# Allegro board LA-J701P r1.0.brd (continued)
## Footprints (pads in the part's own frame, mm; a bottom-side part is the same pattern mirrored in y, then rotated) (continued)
ACES_51524-00401-001_4P
  oval 0.61x1.448 smd: 1(0,0) 2(1,0) 3(2,0) 4(3,0)
  rect 2.388x2.21 smd: 5(-3,-3.125) 6(6,-3.125)
ACES_51612-0340M-P01_34P-T
  oval 0.508x1.245 smd: 1(0,0) 2(0.8,0) 3(1.6,0) 4(2.4,0) 5(3.2,0) 6(4,0) 7(4.8,0) 8(5.6,0) 9(6.4,0) 10(7.2,0) 11(8,0) 12(8.8,0) 13(9.6,0) 14(10.4,0) 15(11.2,0) 16(12,0) 17(12.8,0) 18(13.6,0) 19(14.4,0) 20(15.2,0) 21(16,0) 22(16.8,0) 23(17.6,0) 24(18.4,0) 25(19.2,0) 26(20,0) 27(20.8,0) 28(21.6,0) 29(22.4,0) 30(23.2,0) 31(24,0) 32(24.8,0) 33(25.6,0) 34(26.4,0)
  rect 1.397x1.194 smd: 35(29.075,-3.275) 36(-2.675,-3.275)
ACES_60757-00802-001_8P-T
  oval 0.787x1.295 smd: 1(0,0) 2(-1.25,0) 3(-2.5,0) 4(-3.75,0) 5(-5,0) 6(-6.25,0) 7(-7.5,0) 8(-8.75,0)
  oval 1.041x1.651 hole 0.66x1.245: 9(1.75,-2.8) 10(1.75,-6.275) 11(-10.5,-6.275) 12(-10.5,-2.8)
ALC3287-CG_MQFN48_6X6
  oval 0.889x0.203 smd: 1(0,0) 2(0,-0.4) 3(0,-0.8) 4(0,-1.2) 5(0,-1.6) 6(0,-2) 7(0,-2.4) 8(0,-2.8) 9(0,-3.2) 10(0,-3.6) 11(0,-4) 12(0,-4.4) 25(6.1,-4.4) 26(6.1,-4) 27(6.1,-3.6) 28(6.1,-3.2) 29(6.1,-2.8) 30(6.1,-2.4) 31(6.1,-2) 32(6.1,-1.6) 33(6.1,-1.2) 34(6.1,-0.8) 35(6.1,-0.4) 36(6.1,0)
  oval 0.203x0.889 smd: 13(0.85,-5.25) 14(1.25,-5.25) 15(1.65,-5.25) 16(2.05,-5.25) 17(2.45,-5.25) 18(2.85,-5.25) 19(3.25,-5.25) 20(3.65,-5.25) 21(4.05,-5.25) 22(4.45,-5.25) 23(4.85,-5.25) 24(5.25,-5.25) 37(5.25,0.85) 38(4.85,0.85) 39(4.45,0.85) 40(4.05,0.85) 41(3.65,0.85) 42(3.25,0.85) 43(2.85,0.85) 44(2.45,0.85) 45(2.05,0.85) 46(1.65,0.85) 47(1.25,0.85) 48(0.85,0.85)
  rect 4.394x4.394 smd: 49(3.05,-2.2)
AON6962_DFN5X6D-8-7
  oval 0.66x0.635 smd: 1(0,0) 3(3.81,5.67) 4(2.54,5.67) 5(1.27,5.67) 6(0,5.67)
  custom 0.485x0.485 smd: 2(1.905,0.655)
  rect 3.988x2.667 smd: 7(1.905,3.63)
AON6992_DFN5X6D-8-7
  oval 0.66x0.635 smd: 1(0,0) 3(3.81,5.67) 4(2.54,5.67) 5(1.27,5.67) 6(0,5.67)
  custom 0.485x0.485 smd: 2(1.905,0.655)
  rect 3.988x2.667 smd: 7(1.905,3.62)
AON6994_DFN5X6D-8-7
  oval 0.66x0.635 smd: 1(0,0) 3(3.81,5.67) 4(2.54,5.67) 5(1.27,5.67) 6(0,5.67)
  custom 0.485x0.485 smd: 2(1.905,0.665)
  rect 3.988x2.667 smd: 7(1.905,3.63)
AON7408L_DFN8-5
  oval 0.406x0.991 smd: 1(0,0) 2(0.66,0) 3(1.32,0) 4(1.98,0)
  custom 0.559x0.559 smd: 5(0.99,2.247)
AON7506_DFN3X3-8-5
  oval 0.406x0.991 smd: 1(0,0) 2(0.66,0) 3(1.32,0) 4(1.98,0)
  custom 0.559x0.559 smd: 5(0.99,2.247)
AP2330W-7_SC59-3
  oval 0.787x0.991 smd: 1(0,0) 2(-0.95,-2.4) 3(0.95,-2.4)
AZ5125-02SPR7G_SOT23-3
  oval 1.016x1.524 smd: 1(0,0) 2(0.965,2.083) 3(-0.965,2.083)
AZC099-04SPR7G_SOT23-6
  oval 0.559x1.092 smd: 1(0,0) 2(0.95,0) 3(1.9,0) 4(1.9,2.5) 5(0.95,2.5) 6(0,2.5)
BAT54CW_SOT323-3
  oval 0.711x0.889 smd: 1(0,0) 2(-0.65,-1.9) 3(0.65,-1.9)
BELLW_80152-3221_67P
  round 1.092 hole 1.092 unplated: (-0.75,-5.275)
  round 1.6 hole 1.6 unplated: (19.25,-5.275)
  oval 0.305x1.549 smd: 1(0,0) 2(0.25,-7.55) 3(0.5,0) 4(0.75,-7.55) 5(1,0) 6(1.25,-7.55) 7(1.5,0) 8(1.75,-7.55) 9(2,0) 10(2.25,-7.55) 11(2.5,0) 12(2.75,-7.55) 13(3,0) 14(3.25,-7.55) 15(3.5,0) 16(3.75,-7.55) 17(4,0) 18(4.25,-7.55) 19(4.5,0) 20(4.75,-7.55) 21(5,0) 22(5.25,-7.55) 23(5.5,0) 24(7.75,-7.55) 25(8,0) 26(8.25,-7.55) 27(8.5,0) 28(8.75,-7.55) 29(9,0) 30(9.25,-7.55) 31(9.5,0) 32(9.75,-7.55) 33(10,0) 34(10.25,-7.55) 35(10.5,0) 36(10.75,-7.55) 37(11,0) 38(11.25,-7.55) 39(11.5,0) 40(11.75,-7.55) 41(12,0) 42(12.25,-7.55) 43(12.5,0) 44(12.75,-7.55) 45(13,0) 46(13.25,-7.55) 47(13.5,0) 48(13.75,-7.55) 49(14,0) 50(14.25,-7.55) 51(14.5,0) 52(14.75,-7.55) 53(15,0) 54(15.25,-7.55) 55(15.5,0) 56(15.75,-7.55) 57(16,0) 58(16.25,-7.55) 59(16.5,0) 60(16.75,-7.55) 61(17,0) 62(17.25,-7.55) 63(17.5,0) 64(17.75,-7.55) 65(18,0) 66(18.25,-7.55) 67(18.5,0)
  rect 1.194x2.743 smd: 68(-1.1,-0.775) 69(19.6,-0.775)
BELLW_80159-3221_67P
  round 1.092 hole 1.092 unplated: (-0.75,-5.275)
  round 1.6 hole 1.6 unplated: (19.25,-5.275)
  oval 0.305x1.549 smd: 1(0,0) 2(0.25,-7.55) 3(0.5,0) 4(0.75,-7.55) 5(1,0) 6(1.25,-7.55) 7(1.5,0) 8(1.75,-7.55) 9(2,0) 10(2.25,-7.55) 11(2.5,0) 12(2.75,-7.55) 13(3,0) 14(3.25,-7.55) 15(3.5,0) 16(3.75,-7.55) 17(4,0) 18(4.25,-7.55) 19(4.5,0) 20(4.75,-7.55) 21(5,0) 22(5.25,-7.55) 23(5.5,0) 24(5.75,-7.55) 25(6,0) 26(6.25,-7.55) 27(6.5,0) 28(6.75,-7.55) 29(7,0) 30(7.25,-7.55) 31(7.5,0) 32(7.75,-7.55) 33(8,0) 34(8.25,-7.55) 35(8.5,0) 36(8.75,-7.55) 37(9,0) 38(9.25,-7.55) 39(9.5,0) 40(9.75,-7.55) 41(10,0) 42(10.25,-7.55) 43(10.5,0) 44(10.75,-7.55) 45(11,0) 46(11.25,-7.55) 47(11.5,0) 48(11.75,-7.55) 49(12,0) 50(12.25,-7.55) 51(12.5,0) 52(12.75,-7.55) 53(13,0) 54(13.25,-7.55) 55(13.5,0) 56(13.75,-7.55) 57(14,0) 58(14.25,-7.55) 59(16.5,0) 60(16.75,-7.55) 61(17,0) 62(17.25,-7.55) 63(17.5,0) 64(17.75,-7.55) 65(18,0) 66(18.25,-7.55) 67(18.5,0)
  rect 1.194x2.743 smd: 68(-1.1,-0.775) 69(19.6,-0.775)
BQ25700ARSNR_QFN32_4X4
  oval 0.838x0.203 smd: 1(0,0) 2(0,-0.4) 3(0,-0.8) 4(0,-1.2) 5(0,-1.6) 6(0,-2) 7(0,-2.4) 8(0,-2.8) 17(4.15,-2.8) 18(4.15,-2.4) 19(4.15,-2) 20(4.15,-1.6) 21(4.15,-1.2) 22(4.15,-0.8) 23(4.15,-0.4) 24(4.15,0)
  oval 0.203x0.838 smd: 9(0.675,-3.475) 10(1.075,-3.475) 11(1.475,-3.475) 12(1.875,-3.475) 13(2.275,-3.475) 14(2.675,-3.475) 15(3.075,-3.475) 16(3.475,-3.475) 25(3.475,0.675) 26(3.075,0.675) 27(2.675,0.675) 28(2.275,0.675) 29(1.875,0.675) 30(1.475,0.675) 31(1.075,0.675) 32(0.675,0.675)
  rect 2.794x2.794 smd: 33(2.075,-1.4)
BZT52-B5V1S_SOD323-2
  rect 0.559x0.813 smd: 1(0,0) 2(2.3,0)
C_6P3X4P5
  oval 3.505x1.6 smd: 1(0,0) 2(5.6,0)
C_0201
  rect 0.381x0.356 smd: 1(0,0) 2(0.584,0)
C_0402
  rect 0.508x0.584 smd: 1(0,0) 2(0.914,0)
C_0603
  rect 0.635x0.889 smd: 1(0,0) 2(1.397,0)
C_0805
  rect 0.813x1.397 smd: 1(0,0) 2(1.702,0)
C_D2
  rect 2.388x2.794 smd: 1(0,0) 2(6.4,0)
C_D7
  rect 1.803x2.794 smd: 1(0,0) 2(6.5,0)
C_X
  rect 1.803x2.896 smd: 1(0,0) 2(6,0)
CVILU_CVS3402M1RM-NH_40P
  oval 0.254x1.295 smd: 1(0,0) 2(0.5,0) 3(1,0) 4(1.5,0) 5(2,0) 6(2.5,0) 7(3,0) 8(3.5,0) 9(4,0) 10(4.5,0) 11(5,0) 12(5.5,0) 13(6,0) 14(6.5,0) 15(7,0) 16(7.5,0) 17(8,0) 18(8.5,0) 19(9,0) 20(9.5,0) 21(10,0) 22(10.5,0) 23(11,0) 24(11.5,0) 25(12,0) 26(12.5,0) 27(13,0) 28(13.5,0) 29(14,0) 30(14.5,0) 31(15,0) 32(15.5,0) 33(16,0) 34(16.5,0) 35(17,0) 36(17.5,0) 37(18,0) 38(18.5,0) 39(19,0) 40(19.5,0)
  rect 1.194x3.2 smd: 41(-2.4,1.95) 45(21.9,1.95)
  rect 2.311x1.295 smd: 42(0.85,3.9) 43(9.75,3.9) 44(18.65,3.9)
CYNTE_PCMB103T-2R2MS_2P
  rect 3.81x3.988 smd: 1(0,0) 2(9.2,0)
D_SOD323-2
  rect 0.787x0.889 smd: 1(0,0) 2(2.14,0)
DPS1113FIA-13_QFN18_4X4
  oval 0.762x1.295 smd: 1(0,0) 13(3.85,0)
  oval 0.762x0.305 smd: 2(0,-1) 3(0,-1.5) 4(0,-2) 10(3.85,-2) 11(3.85,-1.5) 12(3.85,-1)
  oval 0.305x0.762 smd: 5(0.925,-2.925) 6(1.425,-2.925) 7(1.925,-2.925) 8(2.425,-2.925) 9(2.925,-2.925)
  rect 2.591x2.972 smd: 14(1.925,-0.813)
DPS1155FEA_V-QFN3025-20_3X2P5
  oval 0.61x0.203 smd: 1(0,0) 2(0,-0.4) 3(0,-0.8) 4(0,-1.2) 5(0,-1.6) 6(0,-2) 9(2.8,-2) 10(2.8,-1.6) 11(2.8,-1.2) 12(2.8,-0.8) 13(2.8,-0.4) 14(2.8,0)
  custom 0.194x0.194 smd: 7(0.913,-1) 8(1.887,-1)
DRAPH_UB11245-B200B-1H_24P-S
  round 0.711 hole 0.711 unplated: (-0.8,-0.776)
  round 0.66 hole 0.66 unplated: (6.55,-0.776)
  oval 0.889x2.311 hole 0.508x1.905: 1(-3.025,-6.876) 3(-2.075,-0.876) 4(7.825,-0.876) 6(8.775,-6.876)
  custom 0.191x0.191 hole 0.711x0.457: 2(-0.9,-1.706)
  oval 1.016x0.762 hole 0.711x0.457: 5(6.65,-1.706)
  oval 0.305x0.787 smd: A1(0,0) A2(0.5,0) A3(1,0) A4(1.5,0) A5(2,0) A6(2.5,0) A7(3,0) A8(3.5,0) A9(4,0) A10(4.5,0) A11(5,0) A12(5.5,0) B1(5.75,-1.452) B2(5.25,-1.452) B3(4.75,-1.452) B4(4.25,-1.452) B5(3.75,-1.452) B6(3.25,-1.452) B7(2.75,-1.452) B8(2.25,-1.452) B9(1.75,-1.452) B10(1.25,-1.452) B11(0.75,-1.452) B12(0.25,-1.452)
EM5201V_DFN8_3X3
  oval 0.305x0.61 smd: 1(0,0) 2(0.65,0) 3(1.3,0) 4(1.95,0) 5(1.95,2.8)
  rect 1.6x0.61 smd: 6(0.65,2.8)
  rect 2.388x1.6 smd: 7(0.975,1.4)
EM5209VF_DFN14_3X2
  oval 0.203x0.711 smd: 1(0,0) 2(0.4,0) 3(0.8,0) 4(1.2,0) 5(1.6,0) 6(2,0) 7(2.4,0) 8(2.4,2) 9(2,2) 10(1.6,2) 11(1.2,2) 12(0.8,2) 13(0.4,2) 14(0,2)
  rect 2.591x0.991 smd: 15(1.2,1)
F75305M_MSOP10
  oval 0.254x1.626 smd: 1(0,0) 2(0.5,0) 3(1,0) 4(1.5,0) 5(2,0) 6(2,4.3) 7(1.5,4.3) 8(1,4.3) 9(0.5,4.3) 10(0,4.3)
  rect 1.6x1.727 smd: 11(1,2.15)
F_F1206HB12V024TM
  rect 1.448x1.803 smd: 1(0,0) 2(2.95,0)
F_F1206HI7000V024TM
  rect 1.448x1.803 smd: 1(0,0) 2(2.95,0)
FIDUCIAL_C40M80
  round 1.016 smd: 1(0,0)
FP6_BGA_1140P-T
  round 0.305 smd: A3(0.9,0) A5(1.8,0) A7(3.3,0) A8(4.3,0) A10(5.3,0) A11(6.3,0) A12(7.3,0) A13(8.3,0) A14(9.3,0) A15(10.3,0) A16(11.3,0) A18(12.3,0) A19(13.3,0) A20(14.3,0) A21(15.3,0) A22(16.3,0) A23(17.3,0) A25(18.3,0) A26(19.3,0) A28(20.8,0) A30(21.7,0) AA1(0,-15.3) AA2(0.4,-14.8) AA3(0.8,-15.3) AA4(1.2,-14.8) AA5(1.9,-15.3) AA13(8.5,-15.1) AA14(9.3,-15.1) AA15(10.1,-15.1) AA16(10.9,-15.1) AA17(11.7,-15.1) AA18(12.5,-15.1) AA19(13.3,-15.1) AA20(14.1,-15.1) AA28(20.7,-15.3) AA29(21.4,-14.8) AA30(21.8,-15.3) AA31(22.2,-14.8) AA32(22.6,-15.3) AB2(0.4,-15.8) AB4(1.2,-15.8) AB13(8.5,-15.9) AB14(9.3,-15.9) AB15(10.1,-15.9) AB16(10.9,-15.9) AB17(11.7,-15.9) AB18(12.5,-15.9) AB19(13.3,-15.9) AB20(14.1,-15.9) AB29(21.4,-15.8) AB31(22.2,-15.8) AC1(0,-16.3) AC2(0.4,-16.8) AC3(0.8,-16.3) AC4(1.2,-16.8) AC5(1.9,-16.3) AC13(8.5,-16.7) AC14(9.3,-16.7) AC15(10.1,-16.7) AC16(10.9,-16.7) AC17(11.7,-16.7) AC18(12.5,-16.7) AC19(13.3,-16.7) AC20(14.1,-16.7) AC28(20.7,-16.3) AC29(21.4,-16.8) AC30(21.8,-16.3) AC31(22.2,-16.8) AC32(22.6,-16.3) AD1(0,-17.3) AD2(0.4,-17.8) AD3(0.8,-17.3) AD4(1.2,-17.8) AD5(1.9,-17.3) AD13(8.5,-17.5) AD14(9.3,-17.5) AD15(10.1,-17.5) AD16(10.9,-17.5) AD17(11.7,-17.5) AD18(12.5,-17.5) AD19(13.3,-17.5) AD20(14.1,-17.5) AD28(20.7,-17.3) AD29(21.4,-17.8) AD30(21.8,-17.3) AD31(22.2,-17.8) AD32(22.6,-17.3) AE1(0,-18.3) AE3(0.8,-18.3) AE5(1.9,-18.3) AE13(8.5,-18.3) AE14(9.3,-18.3) AE15(10.1,-18.3) AE16(10.9,-18.3) AE17(11.7,-18.3) AE18(12.5,-18.3) AE19(13.3,-18.3) AE20(14.1,-18.3) AE28(20.7,-18.3) AE30(21.8,-18.3) AE32(22.6,-18.3) AF1(0,-19.3) AF2(0.4,-18.8) AF3(0.8,-19.3) AF4(1.2,-18.8) AF5(1.9,-19.3) AF13(8.5,-19.1) AF14(9.3,-19.1) AF15(10.1,-19.1) AF16(10.9,-19.1) AF17(11.7,-19.1) AF18(12.5,-19.1) AF19(13.3,-19.1) AF20(14.1,-19.1) AF28(20.7,-19.3) AF29(21.4,-18.8) AF30(21.8,-19.3) AF31(22.2,-18.8) AF32(22.6,-19.3) AG1(0,-20.3) AG2(0.4,-19.8) AG3(0.8,-20.3) AG4(1.2,-19.8) AG5(1.9,-20.3) AG13(8.5,-19.9) AG14(9.3,-19.9) AG15(10.1,-19.9) AG16(10.9,-19.9) AG17(11.7,-19.9) AG18(12.5,-19.9) AG19(13.3,-19.9) AG20(14.1,-19.9) AG28(20.7,-20.3) AG29(21.4,-19.8) AG30(21.8,-20.3) AG31(22.2,-19.8) AG32(22.6,-20.3) AH2(0.4,-20.8) AH4(1.2,-20.8) AH13(8.5,-20.7) AH14(9.3,-20.7) AH15(10.1,-20.7) AH16(10.9,-20.7) AH17(11.7,-20.7) AH18(12.5,-20.7) AH19(13.3,-20.7) AH20(14.1,-20.7) AH29(21.4,-20.8) AH31(22.2,-20.8) AJ1(0,-21.3) AJ2(0.4,-21.8) AJ3(0.8,-21.3) AJ4(1.2,-21.8) AJ5(1.9,-21.3) AJ13(8.5,-21.5) AJ14(9.3,-21.5) AJ15(10.1,-21.5) AJ16(10.9,-21.5) AJ17(11.7,-21.5) AJ18(12.5,-21.5) AJ19(13.3,-21.5) AJ20(14.1,-21.5) AJ28(20.7,-21.3) AJ29(21.4,-21.8) AJ30(21.8,-21.3) AJ31(22.2,-21.8) AJ32(22.6,-21.3) AK1(0,-22.3) AK3(0.8,-22.3) AK5(1.9,-22.3) AK13(8.5,-22.3) AK14(9.3,-22.3) AK15(10.1,-22.3) AK16(10.9,-22.3) AK17(11.7,-22.3) AK18(12.5,-22.3) AK19(13.3,-22.3) AK20(14.1,-22.3) AK28(20.7,-22.3) AK30(21.8,-22.3) AK32(22.6,-22.3) AL1(0,-23.3) AL2(0.4,-22.8) AL3(0.8,-23.3) AL4(1.2,-22.8) AL5(1.9,-23.3) AL13(8.5,-23.1) AL14(9.3,-23.1) AL15(10.1,-23.1) AL16(10.9,-23.1) AL17(11.7,-23.1) AL18(12.5,-23.1) AL19(13.3,-23.1) AL20(14.1,-23.1) AL28(20.7,-23.3) AL29(21.4,-22.8) AL30(21.8,-23.3) AL31(22.2,-22.8) AL32(22.6,-23.3) AM1(0,-24.3) AM2(0.4,-23.8) AM3(0.8,-24.3) AM4(1.2,-23.8) AM5(1.9,-24.3) AM13(8.5,-23.9) AM14(9.3,-23.9) AM15(10.1,-23.9) AM16(10.9,-23.9) AM17(11.7,-23.9) AM18(12.5,-23.9) AM19(13.3,-23.9) AM20(14.1,-23.9) AM28(20.7,-24.3) AM29(21.4,-23.8) AM30(21.8,-24.3) AM31(22.2,-23.8) AM32(22.6,-24.3) AN1(0,-25.3) AN2(0.4,-24.8) AN3(0.8,-25.3) AN4(1.2,-24.8) AN5(1.9,-25.3) AN28(20.7,-25.3) AN29(21.4,-24.8) AN30(21.8,-25.3) AN31(22.2,-24.8) AN32(22.6,-25.3) AP1(0,-26.3) AP2(0.4,-25.8) AP3(0.8,-26.3) AP4(1.2,-25.8) AP5(1.9,-26.3) AP28(20.7,-26.3) AP29(21.4,-25.8) AP30(21.8,-26.3) AP31(22.2,-25.8) AP32(22.6,-26.3) AR1(0,-27.3) AR2(0.4,-26.8) AR3(0.8,-27.3) AR4(1.2,-26.8) AR5(1.9,-27.3) AR28(20.7,-27.3) AR29(21.4,-26.8) AR30(21.8,-27.3) AR31(22.2,-26.8) AR32(22.6,-27.3) AT2(0.4,-27.8) AT4(1.2,-27.8) AT29(21.4,-27.8) AT31(22.2,-27.8) AU1(0,-28.3) AU2(0.4,-28.8) AU3(0.8,-28.3) AU4(1.2,-28.8) AU5(1.9,-28.3) AU28(20.7,-28.3) AU29(21.4,-28.8) AU30(21.8,-28.3) AU31(22.2,-28.8) AU32(22.6,-28.3) AV1(0,-29.3) AV3(0.8,-29.3) AV5(1.9,-29.3) AV28(20.7,-29.3) AV30(21.8,-29.3) AV32(22.6,-29.3) AW2(0.4,-29.8) AW3(0.8,-30.3) AW4(1.2,-29.8) AW5(1.8,-30.3) AW28(20.8,-30.3) AW29(21.4,-29.8) AW30(21.8,-30.3) AW31(22.2,-29.8) AY1(0,-30.8) AY4(1.2,-30.8) AY6(2.3,-30.8) AY7(3.3,-30.7) AY8(4.3,-30.7) AY10(5.3,-30.7) AY11(6.3,-30.7) AY12(7.3,-30.7) AY13(8.3,-30.7) AY14(9.3,-30.7) AY15(10.3,-30.7) AY16(11.3,-30.7) AY18(12.3,-30.7) AY19(13.3,-30.7) AY20(14.3,-30.7) AY21(15.3,-30.7) AY22(16.3,-30.7) AY23(17.3,-30.7) AY25(18.3,-30.7) AY26(19.3,-30.7) AY27(20.3,-30.8) AY29(21.4,-30.8) AY32(22.6,-30.8) B6(2.8,-0.4) B8(3.8,-0.4) B9(4.8,-0.4) B10(5.8,-0.4) B11(6.8,-0.4) B12(7.8,-0.4) B13(8.8,-0.4) B15(9.8,-0.4) B16(10.8,-0.4) B17(11.8,-0.4) B18(12.8,-0.4) B20(13.8,-0.4) B21(14.8,-0.4) B22(15.8,-0.4) B23(16.8,-0.4) B24(17.8,-0.4) B25(18.8,-0.4) B27(19.8,-0.4) BA5(1.8,-31.4) BA6(2.8,-31.4) BA8(3.8,-31.4) BA9(4.8,-31.4) BA10(5.8,-31.4) BA11(6.8,-31.4) BA12(7.8,-31.4) BA13(8.8,-31.4) BA15(9.8,-31.4) BA16(10.8,-31.4) BA17(11.8,-31.4) BA18(12.8,-31.4) BA20(13.8,-31.4) BA21(14.8,-31.4) BA22(15.8,-31.4) BA23(16.8,-31.4) BA24(17.8,-31.4) BA25(18.8,-31.4) BA27(19.8,-31.4) BA28(20.8,-31.4) BB1(0,-31.7) BB3(0.9,-31.7) BB6(2.3,-31.8) BB7(3.3,-31.8) BB8(4.3,-31.8) BB10(5.3,-31.8) BB11(6.3,-31.8) BB12(7.3,-31.8) BB13(8.3,-31.8) BB14(9.3,-31.8) BB15(10.3,-31.8) BB16(11.3,-31.8) BB18(12.3,-31.8) BB19(13.3,-31.8) BB20(14.3,-31.8) BB21(15.3,-31.8) BB22(16.3,-31.8) BB23(17.3,-31.8) BB25(18.3,-31.8) BB26(19.3,-31.8) BB27(20.3,-31.8) BB30(21.7,-31.7) BB32(22.6,-31.7) BC6(2.8,-32.2) BC8(3.8,-32.2) BC9(4.8,-32.2) BC10(5.8,-32.2) BC11(6.8,-32.2) BC12(7.8,-32.2) BC13(8.8,-32.2) BC15(9.8,-32.2) BC16(10.8,-32.2) BC17(11.8,-32.2) BC18(12.8,-32.2) BC20(13.8,-32.2) BC21(14.8,-32.2) BC22(15.8,-32.2) BC23(16.8,-32.2) BC24(17.8,-32.2) BC25(18.8,-32.2) BC27(19.8,-32.2) BD3(0.9,-32.6) BD5(1.8,-32.6) BD7(3.3,-32.6) BD8(4.3,-32.6) BD10(5.3,-32.6) BD11(6.3,-32.6) BD12(7.3,-32.6) BD13(8.3,-32.6) BD14(9.3,-32.6) BD15(10.3,-32.6) BD16(11.3,-32.6) BD18(12.3,-32.6) BD19(13.3,-32.6) BD20(14.3,-32.6) BD21(15.3,-32.6) BD22(16.3,-32.6) BD23(17.3,-32.6) BD25(18.3,-32.6) BD26(19.3,-32.6) BD28(20.8,-32.6) BD30(21.7,-32.6) C1(0,-0.9) C3(0.9,-0.9) C6(2.3,-0.8) C7(3.3,-0.8) C8(4.3,-0.8) C10(5.3,-0.8) C11(6.3,-0.8) C12(7.3,-0.8) C13(8.3,-0.8) C14(9.3,-0.8) C15(10.3,-0.8) C16(11.3,-0.8) C18(12.3,-0.8) C19(13.3,-0.8) C20(14.3,-0.8) C21(15.3,-0.8) C22(16.3,-0.8) C23(17.3,-0.8) C25(18.3,-0.8) C26(19.3,-0.8) C27(20.3,-0.8) C30(21.7,-0.9) C32(22.6,-0.9) D5(1.8,-1.2) D6(2.8,-1.2) D8(3.8,-1.2) D9(4.8,-1.2) D10(5.8,-1.2) D11(6.8,-1.2) D12(7.8,-1.2) D13(8.8,-1.2) D15(9.8,-1.2) D16(10.8,-1.2) D17(11.8,-1.2) D18(12.8,-1.2) D20(13.8,-1.2) D21(14.8,-1.2) D22(15.8,-1.2) D23(16.8,-1.2) D24(17.8,-1.2) D25(18.8,-1.2) D27(19.8,-1.2) D28(20.8,-1.2) E1(0,-1.8) E4(1.2,-1.8) E6(2.3,-1.8) E7(3.3,-1.9) E8(4.3,-1.9) E10(5.3,-1.9) E11(6.3,-1.9) E12(7.3,-1.9) E13(8.3,-1.9) E14(9.3,-1.9) E15(10.3,-1.9) E16(11.3,-1.9) E18(12.3,-1.9) E19(13.3,-1.9) E20(14.3,-1.9) E21(15.3,-1.9) E22(16.3,-1.9) E23(17.3,-1.9) E25(18.3,-1.9) E26(19.3,-1.9) E27(20.3,-1.8) E29(21.4,-1.8) E32(22.6,-1.8) F2(0.4,-2.8) F3(0.8,-2.3) F4(1.2,-2.8) F5(1.8,-2.3) F28(20.8,-2.3) F29(21.4,-2.8) F30(21.8,-2.3) F31(22.2,-2.8) G1(0,-3.3) G3(0.8,-3.3) G5(1.9,-3.3) G28(20.7,-3.3) G30(21.8,-3.3) G32(22.6,-3.3) H1(0,-4.3) H2(0.4,-3.8) H3(0.8,-4.3) H4(1.2,-3.8) H5(1.9,-4.3) H28(20.7,-4.3) H29(21.4,-3.8) H30(21.8,-4.3) H31(22.2,-3.8) H32(22.6,-4.3) J2(0.4,-4.8) J4(1.2,-4.8) J29(21.4,-4.8) J31(22.2,-4.8) K1(0,-5.3) K2(0.4,-5.8) K3(0.8,-5.3) K4(1.2,-5.8) K5(1.9,-5.3) K28(20.7,-5.3) K29(21.4,-5.8) K30(21.8,-5.3) K31(22.2,-5.8) K32(22.6,-5.3) L1(0,-6.3) L2(0.4,-6.8) L3(0.8,-6.3) L4(1.2,-6.8) L5(1.9,-6.3) L28(20.7,-6.3) L29(21.4,-6.8) L30(21.8,-6.3) L31(22.2,-6.8) L32(22.6,-6.3) M1(0,-7.3) M2(0.4,-7.8) M3(0.8,-7.3) M4(1.2,-7.8) M5(1.9,-7.3) M28(20.7,-7.3) M29(21.4,-7.8) M30(21.8,-7.3) M31(22.2,-7.8) M32(22.6,-7.3) N1(0,-8.3) N2(0.4,-8.8) N3(0.8,-8.3) N4(1.2,-8.8) N5(1.9,-8.3) N13(8.5,-8.7) N14(9.3,-8.7) N15(10.1,-8.7) N16(10.9,-8.7) N17(11.7,-8.7) N18(12.5,-8.7) N19(13.3,-8.7) N20(14.1,-8.7) N28(20.7,-8.3) N29(21.4,-8.8) N30(21.8,-8.3) N31(22.2,-8.8) N32(22.6,-8.3) P1(0,-9.3) P2(0.4,-9.8) P3(0.8,-9.3) P4(1.2,-9.8) P5(1.9,-9.3) P13(8.5,-9.5) P14(9.3,-9.5) P15(10.1,-9.5) P16(10.9,-9.5) P17(11.7,-9.5) P18(12.5,-9.5) P19(13.3,-9.5) P20(14.1,-9.5) P28(20.7,-9.3) P29(21.4,-9.8) P30(21.8,-9.3) P31(22.2,-9.8) P32(22.6,-9.3) R1(0,-10.3) R3(0.8,-10.3) R5(1.9,-10.3) R13(8.5,-10.3) R14(9.3,-10.3) R15(10.1,-10.3) R16(10.9,-10.3) R17(11.7,-10.3) R18(12.5,-10.3) R19(13.3,-10.3) R20(14.1,-10.3) R28(20.7,-10.3) R30(21.8,-10.3) R32(22.6,-10.3) T1(0,-11.3) T2(0.4,-10.8) T3(0.8,-11.3) T4(1.2,-10.8) T5(1.9,-11.3) T13(8.5,-11.1) T14(9.3,-11.1) T15(10.1,-11.1) T16(10.9,-11.1) T17(11.7,-11.1) T18(12.5,-11.1) T19(13.3,-11.1) T20(14.1,-11.1) T28(20.7,-11.3) T29(21.4,-10.8) T30(21.8,-11.3) T31(22.2,-10.8) T32(22.6,-11.3) U2(0.4,-11.8) U4(1.2,-11.8) U13(8.5,-11.9) U14(9.3,-11.9) U15(10.1,-11.9) U16(10.9,-11.9) U17(11.7,-11.9) U18(12.5,-11.9) U19(13.3,-11.9) U20(14.1,-11.9) U29(21.4,-11.8) U31(22.2,-11.8) V1(0,-12.3) V2(0.4,-12.8) V3(0.8,-12.3) V4(1.2,-12.8) V5(1.9,-12.3) V13(8.5,-12.7) V14(9.3,-12.7) V15(10.1,-12.7) V16(10.9,-12.7) V17(11.7,-12.7) V18(12.5,-12.7) V19(13.3,-12.7) V20(14.1,-12.7) V28(20.7,-12.3) V29(21.4,-12.8) V30(21.8,-12.3) V31(22.2,-12.8) V32(22.6,-12.3) W1(0,-13.3) W2(0.4,-13.8) W3(0.8,-13.3) W4(1.2,-13.8) W5(1.9,-13.3) W13(8.5,-13.5) W14(9.3,-13.5) W15(10.1,-13.5) W16(10.9,-13.5) W17(11.7,-13.5) W18(12.5,-13.5) W19(13.3,-13.5) W20(14.1,-13.5) W28(20.7,-13.3) W29(21.4,-13.8) W30(21.8,-13.3) W31(22.2,-13.8) W32(22.6,-13.3) Y1(0,-14.3) Y3(0.8,-14.3) Y5(1.9,-14.3) Y13(8.5,-14.3) Y14(9.3,-14.3) Y15(10.1,-14.3) Y16(10.9,-14.3) Y17(11.7,-14.3) Y18(12.5,-14.3) Y19(13.3,-14.3) Y20(14.1,-14.3) Y28(20.7,-14.3) Y30(21.8,-14.3) Y32(22.6,-14.3)
  round 0.406 smd: AA6(2.6,-15.3) AA7(3.3,-15.3) AA8(4.1,-15.3) AA9(4.9,-15.3) AA10(5.7,-15.3) AA11(6.5,-15.3) AA12(7.3,-15.3) AA21(15.3,-15.3) AA22(16.1,-15.3) AA23(16.9,-15.3) AA24(17.7,-15.3) AA25(18.5,-15.3) AA26(19.3,-15.3) AA27(20,-15.3) AC6(2.6,-16.3) AC7(3.3,-16.3) AC8(4.1,-16.3) AC9(4.9,-16.3) AC10(5.7,-16.3) AC11(6.5,-16.3) AC12(7.3,-16.3) AC21(15.3,-16.3) AC22(16.1,-16.3) AC23(16.9,-16.3) AC24(17.7,-16.3) AC25(18.5,-16.3) AC26(19.3,-16.3) AC27(20,-16.3) AD6(2.6,-17.3) AD7(3.3,-17.3) AD8(4.1,-17.3) AD9(4.9,-17.3) AD10(5.7,-17.3) AD11(6.5,-17.3) AD12(7.3,-17.3) AD21(15.3,-17.3) AD22(16.1,-17.3) AD23(16.9,-17.3) AD24(17.7,-17.3) AD25(18.5,-17.3) AD26(19.3,-17.3) AD27(20,-17.3) AE6(2.6,-18.3) AE7(3.3,-18.3) AE8(4.1,-18.3) AE9(4.9,-18.3) AE10(5.7,-18.3) AE11(6.5,-18.3) AE12(7.3,-18.3) AE21(15.3,-18.3) AE22(16.1,-18.3) AE23(16.9,-18.3) AE24(17.7,-18.3) AE25(18.5,-18.3) AE26(19.3,-18.3) AE27(20,-18.3) AF6(2.6,-19.3) AF7(3.3,-19.3) AF8(4.1,-19.3) AF9(4.9,-19.3) AF10(5.7,-19.3) AF11(6.5,-19.3) AF12(7.3,-19.3) AF21(15.3,-19.3) AF22(16.1,-19.3) AF23(16.9,-19.3) AF24(17.7,-19.3) AF25(18.5,-19.3) AF26(19.3,-19.3) AF27(20,-19.3) AG6(2.6,-20.3) AG7(3.3,-20.3) AG8(4.1,-20.3) AG9(4.9,-20.3) AG10(5.7,-20.3) AG11(6.5,-20.3) AG12(7.3,-20.3) AG21(15.3,-20.3) AG22(16.1,-20.3) AG23(16.9,-20.3) AG24(17.7,-20.3) AG25(18.5,-20.3) AG26(19.3,-20.3) AG27(20,-20.3) AJ6(2.6,-21.3) AJ7(3.3,-21.3) AJ8(4.1,-21.3) AJ9(4.9,-21.3) AJ10(5.7,-21.3) AJ11(6.5,-21.3) AJ12(7.3,-21.3) AJ21(15.3,-21.3) AJ22(16.1,-21.3) AJ23(16.9,-21.3) AJ24(17.7,-21.3) AJ25(18.5,-21.3) AJ26(19.3,-21.3) AJ27(20,-21.3) AK6(2.6,-22.3) AK7(3.3,-22.3) AK8(4.1,-22.3) AK9(4.9,-22.3) AK10(5.7,-22.3) AK11(6.5,-22.3) AK12(7.3,-22.3) AK21(15.3,-22.3) AK22(16.1,-22.3) AK23(16.9,-22.3) AK24(17.7,-22.3) AK25(18.5,-22.3) AK26(19.3,-22.3) AK27(20,-22.3) AL6(2.6,-23.3) AL7(3.3,-23.3) AL8(4.1,-23.3) AL9(4.9,-23.3) AL10(5.7,-23.3) AL11(6.5,-23.3) AL12(7.3,-23.3) AL21(15.3,-23.3) AL22(16.1,-23.3) AL23(16.9,-23.3) AL24(17.7,-23.3) AL25(18.5,-23.3) AL26(19.3,-23.3) AL27(20,-23.3) AM6(2.6,-24.3) AM7(3.3,-24.3) AM8(4.1,-24.3) AM9(4.9,-24.3) AM10(5.7,-24.3) AM11(6.5,-24.3) AM12(7.3,-24.3) AM21(15.3,-24.3) AM22(16.1,-24.3) AM23(16.9,-24.3) AM24(17.7,-24.3) AM25(18.5,-24.3) AM26(19.3,-24.3) AM27(20,-24.3) AN6(2.6,-25.3) AN7(3.3,-25.3) AN8(4.1,-25.3) AN9(4.9,-25.3) AN10(5.7,-25.3) AN11(6.5,-25.3) AN12(7.3,-25.3) AN13(8.3,-25.3) AN14(9.3,-25.3) AN15(10.3,-25.3) AN16(11.3,-25.3) AN18(12.3,-25.3) AN19(13.3,-25.3) AN20(14.3,-25.3) AN21(15.3,-25.3) AN22(16.1,-25.3) AN23(16.9,-25.3) AN24(17.7,-25.3) AN25(18.5,-25.3) AN26(19.3,-25.3) AN27(20,-25.3) AP6(2.6,-26.3) AP7(3.3,-26.3) AP8(4.1,-26.3) AP9(4.9,-26.3) AP10(5.7,-26.3) AP12(7.3,-26.1) AP13(8.3,-26.1) AP14(9.3,-26.1) AP15(10.3,-26.1) AP16(11.3,-26.1) AP18(12.3,-26.1) AP19(13.3,-26.1) AP20(14.3,-26.1) AP21(15.3,-26.1) AP23(16.9,-26.3) AP24(17.7,-26.3) AP25(18.5,-26.3) AP26(19.3,-26.3) AP27(20,-26.3) AR6(2.6,-27.3) AR7(3.3,-27.3) AR8(4.1,-27.3) AR11(6.3,-26.9) AR12(7.3,-26.9) AR13(8.3,-26.9) AR14(9.3,-26.9) AR15(10.3,-26.9) AR16(11.3,-26.9) AR18(12.3,-26.9) AR19(13.3,-26.9) AR20(14.3,-26.9) AR21(15.3,-26.9) AR22(16.3,-26.9) AR25(18.5,-27.3) AR26(19.3,-27.3) AR27(20,-27.3) AT10(5.2,-27.4) AT11(6.3,-27.7) AT12(7.3,-27.7) AT13(8.3,-27.7) AT14(9.3,-27.7) AT15(10.3,-27.7) AT16(11.3,-27.7) AT18(12.3,-27.7) AT19(13.3,-27.7) AT20(14.3,-27.7) AT21(15.3,-27.7) AT22(16.3,-27.7) AT23(17.4,-27.4) AU6(2.6,-28.3) AU7(3.3,-28.3) AU8(4.3,-28.3) AU10(5.3,-28.5) AU11(6.3,-28.5) AU12(7.3,-28.5) AU13(8.3,-28.5) AU14(9.3,-28.5) AU15(10.3,-28.5) AU16(11.3,-28.5) AU18(12.3,-28.5) AU19(13.3,-28.5) AU20(14.3,-28.5) AU21(15.3,-28.5) AU22(16.3,-28.5) AU23(17.3,-28.5) AU25(18.3,-28.3) AU26(19.3,-28.3) AU27(20,-28.3) AV6(2.6,-29.3) AV7(3.3,-29.3) AV8(4.3,-29.3) AV10(5.3,-29.3) AV11(6.3,-29.3) AV12(7.3,-29.3) AV13(8.3,-29.3) AV14(9.3,-29.3) AV15(10.3,-29.3) AV16(11.3,-29.3) AV18(12.3,-29.3) AV19(13.3,-29.3) AV20(14.3,-29.3) AV21(15.3,-29.3) AV22(16.3,-29.3) AV23(17.3,-29.3) AV25(18.3,-29.3) AV26(19.3,-29.3) AV27(20,-29.3) AW7(3.3,-30) AW8(4.3,-30) AW10(5.3,-30) AW11(6.3,-30) AW12(7.3,-30) AW13(8.3,-30) AW14(9.3,-30) AW15(10.3,-30) AW16(11.3,-30) AW18(12.3,-30) AW19(13.3,-30) AW20(14.3,-30) AW21(15.3,-30) AW22(16.3,-30) AW23(17.3,-30) AW25(18.3,-30) AW26(19.3,-30) F7(3.3,-2.6) F8(4.3,-2.6) F10(5.3,-2.6) F11(6.3,-2.6) F12(7.3,-2.6) F13(8.3,-2.6) F14(9.3,-2.6) F15(10.3,-2.6) F16(11.3,-2.6) F18(12.3,-2.6) F19(13.3,-2.6) F20(14.3,-2.6) F21(15.3,-2.6) F22(16.3,-2.6) F23(17.3,-2.6) F25(18.3,-2.6) F26(19.3,-2.6) G6(2.6,-3.3) G7(3.3,-3.3) G8(4.3,-3.3) G10(5.3,-3.3) G11(6.3,-3.3) G12(7.3,-3.3) G13(8.3,-3.3) G14(9.3,-3.3) G15(10.3,-3.3) G16(11.3,-3.3) G18(12.3,-3.3) G19(13.3,-3.3) G20(14.3,-3.3) G21(15.3,-3.3) G22(16.3,-3.3) G23(17.3,-3.3) G25(18.3,-3.3) G26(19.3,-3.3) G27(20,-3.3) H6(2.6,-4.3) H7(3.3,-4.3) H8(4.3,-4.3) H10(5.3,-4.1) H11(6.3,-4.1) H12(7.3,-4.1) H13(8.3,-4.1) H14(9.3,-4.1) H15(10.3,-4.1) H16(11.3,-4.1) H18(12.3,-4.1) H19(13.3,-4.1) H20(14.3,-4.1) H21(15.3,-4.1) H22(16.3,-4.1) H23(17.3,-4.1) H25(18.3,-4.3) H26(19.3,-4.3) H27(20,-4.3) J10(5.2,-5.2) J11(6.3,-4.9) J12(7.3,-4.9) J13(8.3,-4.9) J14(9.3,-4.9) J15(10.3,-4.9) J16(11.3,-4.9) J18(12.3,-4.9) J19(13.3,-4.9) J20(14.3,-4.9) J21(15.3,-4.9) J22(16.3,-4.9) J23(17.4,-5.2) K6(2.6,-5.3) K7(3.3,-5.3) K8(4.1,-5.3) K11(6.3,-5.7) K12(7.3,-5.7) K13(8.3,-5.7) K14(9.3,-5.7) K15(10.3,-5.7) K16(11.3,-5.7) K18(12.3,-5.7) K19(13.3,-5.7) K20(14.3,-5.7) K21(15.3,-5.7) K22(16.3,-5.7) K25(18.5,-5.3) K26(19.3,-5.3) K27(20,-5.3) L6(2.6,-6.3) L7(3.3,-6.3) L8(4.1,-6.3) L9(4.9,-6.3) L10(5.7,-6.3) L12(7.3,-6.5) L13(8.3,-6.5) L14(9.3,-6.5) L15(10.3,-6.5) L16(11.3,-6.5) L18(12.3,-6.5) L19(13.3,-6.5) L20(14.3,-6.5) L21(15.3,-6.5) L23(16.9,-6.3) L24(17.7,-6.3) L25(18.5,-6.3) L26(19.3,-6.3) L27(20,-6.3) M6(2.6,-7.3) M7(3.3,-7.3) M8(4.1,-7.3) M9(4.9,-7.3) M10(5.7,-7.3) M11(6.5,-7.3) M12(7.3,-7.3) M13(8.3,-7.3) M14(9.3,-7.3) M15(10.3,-7.3) M16(11.3,-7.3) M18(12.3,-7.3) M19(13.3,-7.3) M20(14.3,-7.3) M21(15.3,-7.3) M22(16.1,-7.3) M23(16.9,-7.3) M24(17.7,-7.3) M25(18.5,-7.3) M26(19.3,-7.3) M27(20,-7.3) N6(2.6,-8.3) N7(3.3,-8.3) N8(4.1,-8.3) N9(4.9,-8.3) N10(5.7,-8.3) N11(6.5,-8.3) N12(7.3,-8.3) N21(15.3,-8.3) N22(16.1,-8.3) N23(16.9,-8.3) N24(17.7,-8.3) N25(18.5,-8.3) N26(19.3,-8.3) N27(20,-8.3) P6(2.6,-9.3) P7(3.3,-9.3) P8(4.1,-9.3) P9(4.9,-9.3) P10(5.7,-9.3) P11(6.5,-9.3) P12(7.3,-9.3) P21(15.3,-9.3) P22(16.1,-9.3) P23(16.9,-9.3) P24(17.7,-9.3) P25(18.5,-9.3) P26(19.3,-9.3) P27(20,-9.3) R6(2.6,-10.3) R7(3.3,-10.3) R8(4.1,-10.3) R9(4.9,-10.3) R10(5.7,-10.3) R11(6.5,-10.3) R12(7.3,-10.3) R21(15.3,-10.3) R22(16.1,-10.3) R23(16.9,-10.3) R24(17.7,-10.3) R25(18.5,-10.3) R26(19.3,-10.3) R27(20,-10.3) T6(2.6,-11.3) T7(3.3,-11.3) T8(4.1,-11.3) T9(4.9,-11.3) T10(5.7,-11.3) T11(6.5,-11.3) T12(7.3,-11.3) T21(15.3,-11.3) T22(16.1,-11.3) T23(16.9,-11.3) T24(17.7,-11.3) T25(18.5,-11.3) T26(19.3,-11.3) T27(20,-11.3) V6(2.6,-12.3) V7(3.3,-12.3) V8(4.1,-12.3) V9(4.9,-12.3) V10(5.7,-12.3) V11(6.5,-12.3) V12(7.3,-12.3) V21(15.3,-12.3) V22(16.1,-12.3) V23(16.9,-12.3) V24(17.7,-12.3) V25(18.5,-12.3) V26(19.3,-12.3) V27(20,-12.3) W6(2.6,-13.3) W7(3.3,-13.3) W8(4.1,-13.3) W9(4.9,-13.3) W10(5.7,-13.3) W11(6.5,-13.3) W12(7.3,-13.3) W21(15.3,-13.3) W22(16.1,-13.3) W23(16.9,-13.3) W24(17.7,-13.3) W25(18.5,-13.3) W26(19.3,-13.3) W27(20,-13.3) Y6(2.6,-14.3) Y7(3.3,-14.3) Y8(4.1,-14.3) Y9(4.9,-14.3) Y10(5.7,-14.3) Y11(6.5,-14.3) Y12(7.3,-14.3) Y21(15.3,-14.3) Y22(16.1,-14.3) Y23(16.9,-14.3) Y24(17.7,-14.3) Y25(18.5,-14.3) Y26(19.3,-14.3) Y27(20,-14.3)
G524B2T11U_SOT23-5
  oval 0.533x1.194 smd: 1(0,0) 2(0.95,0) 3(1.9,0) 4(1.9,3) 5(0,3)
H_2P1N
  round 2.108 hole 2.108 unplated: (0,0)
H_2P3
  round 2.819 hole 2.311: 1(0,0)
H_2P8
  round 3.302 hole 2.794: 1(0,0)
H_3P1X2P1N
  oval 3.099x2.108 hole 3.099x2.108 unplated: (0,0)
H_3P2
  round 3.708 hole 3.2: 1(0,0)
H_3P3
  round 3.81 hole 3.302: 1(0,0)
H_3P5
  round 4.013 hole 3.505: 1(0,0)
HRS_TF31-40S-0P5SH-800_40P
  oval 0.305x1.092 smd: 1(0,0) 2(0.5,0) 3(1,0) 4(1.5,0) 5(2,0) 6(2.5,0) 7(3,0) 8(3.5,0) 9(4,0) 10(4.5,0) 11(5,0) 12(5.5,0) 13(6,0) 14(6.5,0) 15(7,0) 16(7.5,0) 17(8,0) 18(8.5,0) 19(9,0) 20(9.5,0) 21(10,0) 22(10.5,0) 23(11,0) 24(11.5,0) 25(12,0) 26(12.5,0) 27(13,0) 28(13.5,0) 29(14,0) 30(14.5,0) 31(15,0) 32(15.5,0) 33(16,0) 34(16.5,0) 35(17,0) 36(17.5,0) 37(18,0) 38(18.5,0) 39(19,0) 40(19.5,0)
  rect 0.787x2.489 smd: 41(-1.7,-3.6) 42(21.2,-3.6)
INPAQ_HCM1012GH900BP_4P
  rect 0.711x0.305 smd: 1(0,0) 2(1.25,0) 3(1.25,-0.5) 4(0,-0.5)
JUMP_43X39
  custom 0.191x0.191 smd: 1(0,0) 2(0.914,0)
JUMP_43X79
  custom 0.188x0.188 smd: 1(0,0) 2(1.1,0)
JUMP_43X118
  custom 0.187x0.187 smd: 1(0,0) 2(1.1,0)
JXT_WB201H-004G10M_4P
  oval 0.787x1.905 smd: 1(0,0) 2(1.25,0) 3(2.5,0) 4(3.75,0)
  rect 1.295x3.353 smd: 5(-2.85,-4.875) 6(6.6,-4.875)
K4AAG165WA-BCWE_FBGA_96P
  round 0.343 smd: A1(0,0) A2(0.8,0) A3(1.6,0) A7(4.801,0) A8(5.601,0) A9(6.401,0) B1(0,-0.8) B2(0.8,-0.8) B3(1.6,-0.8) B7(4.801,-0.8) B8(5.601,-0.8) B9(6.401,-0.8) C1(0,-1.6) C2(0.8,-1.6) C3(1.6,-1.6) C7(4.801,-1.6) C8(5.601,-1.6) C9(6.401,-1.6) D1(0,-2.4) D2(0.8,-2.4) D3(1.6,-2.4) D7(4.801,-2.4) D8(5.601,-2.4) D9(6.401,-2.4) E1(0,-3.2) E2(0.8,-3.2) E3(1.6,-3.2) E7(4.801,-3.2) E8(5.601,-3.2) E9(6.401,-3.2) F1(0,-4) F2(0.8,-4) F3(1.6,-4) F7(4.801,-4) F8(5.601,-4) F9(6.401,-4) G1(0,-4.801) G2(0.8,-4.801) G3(1.6,-4.801) G7(4.801,-4.801) G8(5.601,-4.801) G9(6.401,-4.801) H1(0,-5.601) H2(0.8,-5.601) H3(1.6,-5.601) H7(4.801,-5.601) H8(5.601,-5.601) H9(6.401,-5.601) J1(0,-6.401) J2(0.8,-6.401) J3(1.6,-6.401) J7(4.801,-6.401) J8(5.601,-6.401) J9(6.401,-6.401) K1(0,-7.201) K2(0.8,-7.201) K3(1.6,-7.201) K7(4.801,-7.201) K8(5.601,-7.201) K9(6.401,-7.201) L1(0,-8.001) L2(0.8,-8.001) L3(1.6,-8.001) L7(4.801,-8.001) L8(5.601,-8.001) L9(6.401,-8.001) M1(0,-8.801) M2(0.8,-8.801) M3(1.6,-8.801) M7(4.801,-8.801) M8(5.601,-8.801) M9(6.401,-8.801) N1(0,-9.601) N2(0.8,-9.601) N3(1.6,-9.601) N7(4.801,-9.601) N8(5.601,-9.601) N9(6.401,-9.601) P1(0,-10.401) P2(0.8,-10.401) P3(1.6,-10.401) P7(4.801,-10.401) P8(5.601,-10.401) P9(6.401,-10.401) R1(0,-11.201) R2(0.8,-11.201) R3(1.6,-11.201) R7(4.801,-11.201) R8(5.601,-11.201) R9(6.401,-11.201) T1(0,-12.002) T2(0.8,-12.002) T3(1.6,-12.002) T7(4.801,-12.002) T8(5.601,-12.002) T9(6.401,-12.002)
KB9022QD_LQFP128_14X14
  oval 1.753x0.203 smd: 1(0,0) 2(0,-0.4) 3(0,-0.8) 4(0,-1.2) 5(0,-1.6) 6(0,-2) 7(0,-2.4) 8(0,-2.8) 9(0,-3.2) 10(0,-3.6) 11(0,-4) 12(0,-4.4) 13(0,-4.8) 14(0,-5.2) 15(0,-5.6) 16(0,-6) 17(0,-6.4) 18(0,-6.8) 19(0,-7.2) 20(0,-7.6) 21(0,-8) 22(0,-8.4) 23(0,-8.8) 24(0,-9.2) 25(0,-9.6) 26(0,-10) 27(0,-10.4) 28(0,-10.8) 29(0,-11.2) 30(0,-11.6) 31(0,-12) 32(0,-12.4) 65(15.654,-12.4) 66(15.654,-12) 67(15.654,-11.6) 68(15.654,-11.2) 69(15.654,-10.8) 70(15.654,-10.4) 71(15.654,-10) 72(15.654,-9.6) 73(15.654,-9.2) 74(15.654,-8.8) 75(15.654,-8.4) 76(15.654,-8) 77(15.654,-7.6) 78(15.654,-7.2) 79(15.654,-6.8) 80(15.654,-6.4) 81(15.654,-6) 82(15.654,-5.6) 83(15.654,-5.2) 84(15.654,-4.8) 85(15.654,-4.4) 86(15.654,-4) 87(15.654,-3.6) 88(15.654,-3.2) 89(15.654,-2.8) 90(15.654,-2.4) 91(15.654,-2) 92(15.654,-1.6) 93(15.654,-1.2) 94(15.654,-0.8) 95(15.654,-0.4) 96(15.654,0)
  oval 0.203x1.753 smd: 33(1.627,-14.027) 34(2.027,-14.027) 35(2.427,-14.027) 36(2.827,-14.027) 37(3.227,-14.027) 38(3.627,-14.027) 39(4.027,-14.027) 40(4.427,-14.027) 41(4.827,-14.027) 42(5.227,-14.027) 43(5.627,-14.027) 44(6.027,-14.027) 45(6.427,-14.027) 46(6.827,-14.027) 47(7.227,-14.027) 48(7.627,-14.027) 49(8.027,-14.027) 50(8.427,-14.027) 51(8.827,-14.027) 52(9.227,-14.027) 53(9.627,-14.027) 54(10.027,-14.027) 55(10.427,-14.027) 56(10.827,-14.027) 57(11.227,-14.027) 58(11.627,-14.027) 59(12.027,-14.027) 60(12.427,-14.027) 61(12.827,-14.027) 62(13.227,-14.027) 63(13.627,-14.027) 64(14.027,-14.027) 97(14.027,1.627) 98(13.627,1.627) 99(13.227,1.627) 100(12.827,1.627) 101(12.427,1.627) 102(12.027,1.627) 103(11.627,1.627) 104(11.227,1.627) 105(10.827,1.627) 106(10.427,1.627) 107(10.027,1.627) 108(9.627,1.627) 109(9.227,1.627) 110(8.827,1.627) 111(8.427,1.627) 112(8.027,1.627) 113(7.627,1.627) 114(7.227,1.627) 115(6.827,1.627) 116(6.427,1.627) 117(6.027,1.627) 118(5.627,1.627) 119(5.227,1.627) 120(4.827,1.627) 121(4.427,1.627) 122(4.027,1.627) 123(3.627,1.627) 124(3.227,1.627) 125(2.827,1.627) 126(2.427,1.627) 127(2.027,1.627) 128(1.627,1.627)
L2N7002WT1G_SC70-3
  oval 0.711x0.889 smd: 1(0,0) 2(0.65,1.9) 3(-0.65,1.9)
L2N7002WT1G_SC-70-3
  oval 0.711x0.889 smd: 1(0,0) 2(-0.65,-1.9) 3(0.65,-1.9)
L_5X5X3_M
  custom 0.54x0.54 smd: 1(0,0) 4(4.35,0)
  rect 0.762x0.508 smd: 2(0.699,0) 3(3.652,0)
L_5X5X3_M_2P
  rect 2.159x2.794 smd: 1(0,0) 2(4.35,0)
L_7X7X3_M
  custom 0.591x0.591 smd: 1(0,0) 4(6.05,0)
  rect 0.762x0.508 smd: 2(0.8,0) 3(5.25,0)
LBSS84LT1G_SOT23-3
  oval 1.016x1.524 smd: 1(0,0) 2(0.965,2.083) 3(-0.965,2.083)
LBSS138LT1G_SOT23-3
  oval 1.016x1.524 smd: 1(0,0) 2(0.965,2.083) 3(-0.965,2.083)
LBSS139WT1G_SC70-3
  oval 0.711x0.889 smd: 1(0,0) 2(-0.65,-1.9) 3(0.65,-1.9)
LED_LTST-C191KFKT-2CA_2P
  rect 0.787x0.787 smd: 1(0,0) 2(1.5,0)
LED_LTW-110DC5-C_3P
  rect 1.194x0.787 smd: 1(0,0) 2(3,0)
  rect 0.889x0.889 smd: 3(1.5,-0.55)
LED_LTW-C193TS5-C_2P
  rect 0.787x0.787 smd: 1(0,0) 2(1.5,0)
LOTES_AHDM0064-P001A_19P
  round 0.787 hole 0.559: 1(0,0) 2(0.5,1.55) 3(1,0) 4(1.5,1.55) 5(2,0) 6(2.5,1.55) 7(3,0) 8(3.5,1.55) 9(4,0) 10(4.5,1.55) 11(5,0) 12(5.5,1.55) 13(6,0) 14(6.5,1.55) 15(7,0) 16(7.5,1.55) 17(8,0) 18(8.5,1.55) 19(9,0)
  oval 1.499x2.21 hole 0.889x1.6: 20(-2.75,1.7) 21(-4.65,-6.5) 22(11.75,1.7) 23(13.65,-7.75)
LSK3541G1ET2L_VMT3
  oval 0.508x0.457 smd: 1(0,0)
  oval 0.406x0.457 smd: 2(-0.4,-1.15) 3(0.4,-1.15)
MC74VHC1G08DFT2G_SC70-5
  oval 0.381x0.711 smd: 1(0,0) 2(0.65,0) 3(1.3,0) 4(1.3,1.9) 5(0,1.9)
ME2301DC-G_SOT23-3
  oval 1.016x1.524 smd: 1(0,0) 2(0.965,2.083) 3(-0.965,2.083)
METR3906KW-G_SOT363-6
  oval 0.406x0.508 smd: 1(0,0) 2(0.65,0) 3(1.3,0) 4(1.3,1.9) 5(0.65,1.9) 6(0,1.9)
MMST3904-7-F_SOT323-3
  oval 0.711x0.889 smd: 1(0,0) 2(0.65,1.9) 3(-0.65,1.9)
MURAT_BLM15AX300SN1D_2P
  rect 0.457x0.508 smd: 1(0,0) 2(0.85,0)
MURAT_BLM15BD121SN1D_2P
  rect 0.457x0.508 smd: 1(0,0) 2(0.85,0)
MURAT_BLM15PX221SN1D_2P
  rect 0.457x0.508 smd: 1(0,0) 2(0.85,0)
MURAT_DLM0NSN900HY2D_4P
  rect 0.305x0.305 smd: 1(0,0) 2(0.6,0) 3(0.6,-0.5) 4(0,-0.5)
NC7SZ08P5X_NL_SC70-5
  oval 0.457x0.711 smd: 1(-0.65,-0.925) 2(0,-0.925) 3(0.65,-0.925) 4(0.65,0.925) 5(-0.65,0.925)
NC7WV07P6X_SC70-6
  oval 0.406x0.508 smd: 1(0,0) 2(0.65,0) 3(1.3,0) 4(1.3,1.9) 5(0.65,1.9) 6(0,1.9)
NSR20F30NXT5G_DSN2-2
  rect 0.432x0.711 smd: 1(-0.05,0)
  rect 0.787x0.508 smd: 2(0.94,0)
PESD24VS2UT_SOT23-3
  oval 1.016x1.524 smd: 1(0,0) 2(0.965,2.083) 3(-0.965,2.083)
PSOT24C_SOT23-3
  oval 1.016x1.524 smd: 1(0,0) 2(0.965,2.083) 3(-0.965,2.083)
PUSB3FR4_DFN2510A10-10
  oval 0.254x0.889 smd: 1(0,0)
  oval 0.254x0.838 smd: 2(0.5,-0.025) 3(1,-0.025) 4(1.5,-0.025) 5(2,-0.025) 6(2,1.225) 7(1.5,1.225) 8(1,1.225) 9(0.5,1.225) 10(0,1.225)
Q_P_DFN33-8-5
  oval 0.406x0.991 smd: 1(0,0) 2(0.65,0) 3(1.3,0) 4(1.95,0)
  custom 0.625x0.625 smd: 5(0.975,2.15)
R0402_0OHM
  custom 0.14x0.14 smd: 1(0,0)
  rect 0.508x0.559 smd: 2(0.914,0)
R0603_0OHM
  custom 0.222x0.222 smd: 1(0,0)
  rect 0.635x0.889 smd: 2(1.397,0)
R0805_0OHM
  custom 0.349x0.349 smd: 1(0,0)
  rect 0.813x1.397 smd: 2(1.702,0)
R_0201
  rect 0.381x0.356 smd: 1(0,0) 2(0.584,0)
R_0402
  rect 0.508x0.559 smd: 1(0,0) 2(0.914,0)
R_0402-X
  rect 0.428x0.559 smd: 1(0,0) 2(0.834,0)
R_0603
  rect 0.635x0.889 smd: 1(0,0) 2(1.397,0)
R_0805
  rect 0.813x1.397 smd: 1(0,0) 2(1.702,0)
R_1206
  rect 1.016x1.651 smd: 1(0,0) 2(2.667,0)
R_1206_4P-D
  custom 0.371x0.371 smd: 1(0,0) 4(3.327,0)
  custom 0.114x0.114 smd: 2(0.775,0) 3(2.553,0)
RB751V-40_SOD323-2
  rect 0.787x0.889 smd: 1(0,0) 2(2.14,0)
RT3663BHGQW_WQFN52_6X6
  oval 0.889x0.254 smd: 1(0,0) 2(0,-0.4) 3(0,-0.8) 4(0,-1.2) 5(0,-1.6) 6(0,-2) 7(0,-2.4) 8(0,-2.8) 9(0,-3.2) 10(0,-3.6) 11(0,-4) 12(0,-4.4) 13(0,-4.8) 27(5.95,-4.8) 28(5.95,-4.4) 29(5.95,-4) 30(5.95,-3.6) 31(5.95,-3.2) 32(5.95,-2.8) 33(5.95,-2.4) 34(5.95,-2) 35(5.95,-1.6) 36(5.95,-1.2) 37(5.95,-0.8) 38(5.95,-0.4) 39(5.95,0)
  oval 0.254x0.889 smd: 14(0.575,-5.375) 15(0.975,-5.375) 16(1.375,-5.375) 17(1.775,-5.375) 18(2.175,-5.375) 19(2.575,-5.375) 20(2.975,-5.375) 21(3.375,-5.375) 22(3.775,-5.375) 23(4.175,-5.375) 24(4.575,-5.375) 25(4.975,-5.375) 26(5.375,-5.375) 40(5.375,0.575) 41(4.975,0.575) 42(4.575,0.575) 43(4.175,0.575) 44(3.775,0.575) 45(3.375,0.575) 46(2.975,0.575) 47(2.575,0.575) 48(2.175,0.575) 49(1.775,0.575) 50(1.375,0.575) 51(0.975,0.575) 52(0.575,0.575)
  rect 4.699x4.699 smd: 53(2.975,-2.4)
RT8207PGQW_WQFN20_3X3
  oval 0.203x0.889 smd: 1(0,0) 2(0.4,0) 3(0.8,0) 4(1.2,0) 5(1.6,0) 11(1.6,3.1) 12(1.2,3.1) 13(0.8,3.1) 14(0.4,3.1) 15(0,3.1)
  oval 0.889x0.203 smd: 6(2.35,0.75) 7(2.35,1.15) 8(2.35,1.55) 9(2.35,1.95) 10(2.35,2.35) 16(-0.75,2.35) 17(-0.75,1.95) 18(-0.75,1.55) 19(-0.75,1.15) 20(-0.75,0.75)
  rect 1.702x1.702 smd: 21(0.8,1.55)
RT9059GQW_WDFN10_3X3
  oval 0.254x0.889 smd: 1(0,0) 2(0.5,0) 3(1,0) 4(1.5,0) 5(2,0) 6(2,3.1) 7(1.5,3.1) 8(1,3.1) 9(0.5,3.1) 10(0,3.1)
  rect 2.464x1.626 smd: 11(1,1.55)
RT9610CGQW_WDFN8_2X2
  oval 0.254x0.838 smd: 1(0,0) 2(0.5,0) 3(1,0) 4(1.5,0) 5(1.5,2.15) 6(1,2.15) 7(0.5,2.15) 8(0,2.15)
  rect 1.118x0.533 smd: 9(0.75,1.075)
RTS5457V-GR_QFN40_5X5
  oval 0.762x0.254 smd: 1(0,0) 2(0,-0.4) 3(0,-0.8) 4(0,-1.2) 5(0,-1.6) 6(0,-2) 7(0,-2.4) 8(0,-2.8) 9(0,-3.2) 10(0,-3.6) 21(4.9,-3.6) 22(4.9,-3.2) 23(4.9,-2.8) 24(4.9,-2.4) 25(4.9,-2) 26(4.9,-1.6) 27(4.9,-1.2) 28(4.9,-0.8) 29(4.9,-0.4) 30(4.9,0)
  oval 0.254x0.762 smd: 11(0.65,-4.25) 12(1.05,-4.25) 13(1.45,-4.25) 14(1.85,-4.25) 15(2.25,-4.25) 16(2.65,-4.25) 17(3.05,-4.25) 18(3.45,-4.25) 19(3.85,-4.25) 20(4.25,-4.25) 31(4.25,0.65) 32(3.85,0.65) 33(3.45,0.65) 34(3.05,0.65) 35(2.65,0.65) 36(2.25,0.65) 37(1.85,0.65) 38(1.45,0.65) 39(1.05,0.65) 40(0.65,0.65)
  rect 3.708x3.708 smd: 41(2.45,-1.8)
SAMTE_ASP-136446-07-B_20P-T
  oval 0.737x2.794 smd: 1(0,0) 2(0,4.07) 3(1.27,0) 4(1.27,4.07) 5(2.54,0) 6(2.54,4.07) 7(3.81,0) 8(3.81,4.07) 9(5.08,0) 10(5.08,4.07) 11(6.35,0) 12(6.35,4.07) 13(7.62,0) 14(7.62,4.07) 15(8.89,0) 16(8.89,4.07) 17(10.16,0) 18(10.16,4.07) 19(11.43,0) 20(11.43,4.07)
SHORTPADS
  custom 0.19x0.19 smd: 1(-0.483,0) 2(0.483,0)
SN74AHC1G08DCKR_SC70-5
  oval 0.381x1.295 smd: 1(0,0.15) 2(0.65,0.15) 3(1.3,0.15) 4(1.3,1.89) 5(0,1.89)
SN74LVC1G07DCKR_SC70-5
  oval 0.381x0.864 smd: 1(0,0) 2(0.65,0) 3(1.3,0) 4(1.3,1.74) 5(0,1.74)
SW_TBF313KQR_5P
  rect 1.651x1.041 smd: 1(0,0) 2(-3.85,0)
  rect 1.651x1.041 hole 0.66: 3(0.1,1.525) 4(-3.95,1.525)
  rect 1.092x0.508 smd: 5(-1.925,-0.975)
SY6288C20AAC_SOT23-5
  oval 0.559x0.787 smd: 1(0,0) 2(0.95,0) 3(1.9,0) 4(1.9,2.4) 5(0,2.4)
SY6288D20AAC_SOT23-5
  oval 0.559x0.787 smd: 1(0,0) 2(0.95,0) 3(1.9,0) 4(1.9,2.4) 5(0,2.4)
SY8284RAC_QFN20_3X3
  oval 0.889x0.254 smd: 1(0,0) 2(0,-0.45) 3(0,-0.9) 4(0,-1.35) 5(0,-1.8) 11(3.1,-1.8) 12(3.1,-1.35) 13(3.1,-0.9) 14(3.1,-0.45) 15(3.1,0)
  oval 0.254x0.889 smd: 6(0.65,-2.45) 7(1.1,-2.45) 8(1.55,-2.45) 9(2,-2.45) 10(2.45,-2.45) 16(2.45,0.65) 17(2,0.65) 18(1.55,0.65) 19(1.1,0.65) 20(0.65,0.65)
  custom 0.125x0.125 smd: 21(1.55,-0.9)
SY8288CRAC_QFN20_3X3
  oval 0.889x0.254 smd: 1(0,0) 2(0,-0.45) 3(0,-0.9) 4(0,-1.35) 5(0,-1.8) 11(3.1,-1.8) 12(3.1,-1.35) 13(3.1,-0.9) 14(3.1,-0.45) 15(3.1,0)
  oval 0.254x0.889 smd: 6(0.65,-2.45) 7(1.1,-2.45) 8(1.55,-2.45) 9(2,-2.45) 10(2.45,-2.45) 16(2.45,0.65) 17(2,0.65) 18(1.55,0.65) 19(1.1,0.65) 20(0.65,0.65)
  rect 0.991x0.991 smd: 21(1.55,-0.9)
SY8386RHC_QFN16_2P5X2P5
  custom 0.064x0.064 smd: 1(0,0) 4(0,-1.35) 5(0.625,-1.975) 8(1.975,-1.975) 9(2.6,-1.35) 12(2.6,0) 13(1.975,0.625) 16(0.625,0.625)
  oval 0.889x0.254 smd: 2(0,-0.45) 3(0,-0.9) 10(2.6,-0.9) 11(2.6,-0.45)
  oval 0.254x0.889 smd: 6(1.075,-1.975) 7(1.525,-1.975) 14(1.525,0.625) 15(1.075,0.625)
  rect 0.61x0.61 smd: 17(1.3,-0.675)
SY8388BRHC_QFN16_2P5X2P5
  custom 0.064x0.064 smd: 1(0,0) 4(0,-1.35) 5(0.625,-1.975) 8(1.975,-1.975) 9(2.6,-1.35) 12(2.6,0) 13(1.975,0.625) 16(0.625,0.625)
  oval 0.889x0.254 smd: 2(0,-0.45) 3(0,-0.9) 10(2.6,-0.9) 11(2.6,-0.45)
  oval 0.254x0.889 smd: 6(1.075,-1.975) 7(1.525,-1.975) 14(1.525,0.625) 15(1.075,0.625)
  rect 0.711x0.787 smd: 17(1.3,-0.675)
TAI-T_TMPC0412HP-1R5M-Z02_2P
  rect 1.499x2.311 smd: 1(0,0) 2(3.7,0)
TPC12
  round 0.305 smd: 1(0,0)
TPD6S300ARUKR_WQFN20_3X3
  oval 0.838x0.254 smd: 1(0,0) 2(0,-0.4) 3(0,-0.8) 4(0,-1.2) 5(0,-1.6) 11(3,-1.6) 12(3,-1.2) 13(3,-0.8) 14(3,-0.4) 15(3,0)
  oval 0.254x0.838 smd: 6(0.7,-2.3) 7(1.1,-2.3) 8(1.5,-2.3) 9(1.9,-2.3) 10(2.3,-2.3) 16(2.3,0.7) 17(1.9,0.7) 18(1.5,0.7) 19(1.1,0.7) 20(0.7,0.7)
  rect 1.803x1.803 smd: 21(1.5,-0.8)
TPS2546RTER_QFN16_3X3-S
  oval 0.254x0.889 smd: 1(0,0) 2(0.5,0) 3(1,0) 4(1.5,0) 9(1.5,3.1) 10(1,3.1) 11(0.5,3.1) 12(0,3.1)
  oval 0.889x0.254 smd: 5(2.3,0.8) 6(2.3,1.3) 7(2.3,1.8) 8(2.3,2.3) 13(-0.8,2.3) 14(-0.8,1.8) 15(-0.8,1.3) 16(-0.8,0.8)
  rect 1.651x1.651 smd: 17(0.75,1.55)
W25Q128FWSIQ_SO8
  oval 0.635x1.676 smd: 1(0,0) 2(1.27,0) 3(2.54,0) 4(3.81,0) 5(3.81,7.25) 6(2.54,7.25) 7(1.27,7.25) 8(0,7.25)
Y_X1A000141000200_2P
  rect 0.991x1.803 smd: 1(0,0) 2(2.5,0)
Y_X3S048000D81H-W_4P
  rect 1.397x1.194 smd: 1(0,0) 2(2.2,0) 3(2.2,1.7) 4(0,1.7)
YSCLAMP0524P_SLP2510P8-10-9
  oval 0.203x0.686 smd: 1(0,0) 2(0.5,0) 4(1.5,0) 5(2,0) 6(2,0.875) 7(1.5,0.875) 8(0.5,0.875) 9(0,0.875)
  oval 0.406x1.549 smd: 3(1,0.438)
YUQIU_1603046-01611_6P
  oval 0.991x1.499 hole 0.508x0.991: 1(0,0)
  oval 0.991x1.651 hole 0.508x1.143: 2(8.7,-0.21) 3(8.7,2.79) 4(8.7,6.8) 5(0,3.32) 6(0,7.2)

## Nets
0.75VS_PWR_EN: R70.2 U19.4 UEC1.98
1.8VALW_PG: PR601.1 PR1812.2 PU1802.7
1.8VALW_PWR_EN#: Q202.2 Q202.3 R74.2
1.8VS_PWR_EN#: Q146.2 R67.2 UEC1.99
1.8VS_PWR_EN_GATE: Q146.1 R185.1 R2752.1
1.8VS_PWR_EN_R_GATE: C316.1 Q5.2 R185.2
2.5V_EN: PC255.1 PR251.2 PR256.2 PU251.6
2.5V_FB: PR252.2 PR254.1 PU251.4
2.5V_VIN: PC253.1 PJ251.2 PU251.7 PU251.8 PU251.9
3V/5VALW_PG: C258.2 PR303.2 PR1807.1 PU301.7 PU501.9 Q202.5 UEC1.101
3V_FB: PC313.1 PU301.10
3V_FB_1: PC313.2 PR304.1
3V_SN: PC312.1 PR302.2
5V_3V_EN: PC522.1 PR503.1 PR509.2 PR510.2 PR512.1 PU301.9
5V_EN: PC521.1 PR503.2 PR507.2 PR508.2 PR511.1 PU501.12
5V_FB: PC519.1 PU501.13
5V_FB_1: PC519.2 PR505.1
5V_SN: PC517.1 PR502.2
+0.6V_DDRA_VREFCA: CD1.1 CD2.1 CD6.2 CD7.2 CD8.1 CD9.1 CD34.1 CD36.1 CD38.1 CD40.1 RD32.1 RD37.2 UD1.M1 UD2.M1 UD3.M1 UD4.M1
+0.6V_DDRB_VREFCA: CD57.2 CD58.2 CD59.1 CD60.1 CD61.1 CD62.1 CD91.1 CD92.1 CD93.1 CD94.1 RD46.1 RD47.2 UD5.M1 UD6.M1 UD7.M1 UD8.M1
+0.6VS: CD28.1 CD29.1 CD30.1 CD31.1 CD32.1 CD33.2 CD35.2 CD37.2 CD39.2 CD41.2 CD81.1 CD82.1 CD83.1 CD84.1 CD85.1 CD86.2 CD87.2 CD88.2 CD89.2 CD90.2 CD113.1 CD114.1 PJM3.2 RD2.1 RD3.1 RD4.1 RD5.1 RD6.1 RD7.1 RD8.1 RD9.1 RD10.1 RD11.1 RD12.1 RD13.1 RD14.1 RD15.1 RD16.1 RD17.1 RD18.1 RD19.1 RD20.1 RD21.1 RD22.1 RD23.1 RD24.1 RD25.1 RD26.1 RD27.1 RD43.1 RD56.1 RD57.1 RD58.1 RD59.1 RD60.1 RD61.1 RD62.1 RD63.1 RD64.1 RD65.1 RD66.1 RD67.1 RD68.1 RD69.1 RD71.1 RD72.1 RD73.1 RD74.1 RD75.1 RD76.1 RD77.1 RD78.1 RD79.1 RD80.1 RD81.1
+0.6VSP: PCM18.1 PCM19.1 PJM3.1 PUM1.2 PUM1.20
+0.75VALW: C236.1 C237.1 CC64.1 CC65.1 CC66.1 CC67.1 PJ601.2 U19.1 U19.2 U19.7 UC1.AL11 UC1.AL12 UC1.AM12
+0.75VALW_0.75VS: J6.2 U19.6
+0.75VALWP: PC606.1 PC607.1 PC608.1 PC609.1 PC610.1 PC611.1 PC613.1 PJ601.1 PL602.2 PR610.1
+0.75VS: C242.1 C243.1 CC53.1 CC54.1 CC55.1 CC56.1 CC57.1 CC58.1 CC59.1 CC60.1 CC61.1 CC62.1 CC63.1 CC115.1 J6.1 RC22.2 UC1.M15 UC1.M16 UC1.M18
+1.2V: CC35.1 CC36.1 CC37.1 CC38.1 CC39.1 CC40.1 CC43.1 CC44.1 CC45.1 CC46.1 CC47.1 CC48.1 CC49.1 CC50.1 CC51.1 CC52.1 CC116.1 CC117.1 CC118.1 CC119.1 CD3.1 CD5.2 CD10.1 CD11.1 CD12.1 CD13.1 CD14.1 CD15.1 CD16.1 CD17.1 CD18.1 CD19.1 CD20.1 CD21.1 CD22.1 CD23.1 CD24.1 CD25.1 CD26.1 CD27.1 CD33.1 CD34.2 CD35.1 CD36.2 CD37.1 CD38.2 CD39.1 CD40.2 CD41.1 CD54.1 CD56.2 CD63.1 CD64.1 CD65.1 CD66.1 CD67.1 CD68.1 CD69.1 CD70.1 CD71.1 CD72.1 CD73.1 CD74.1 CD75.1 CD76.1 CD77.1 CD78.1 CD79.1 CD80.1 CD86.1 CD87.1 CD88.1 CD89.1 CD90.1 CD91.2 CD92.2 CD93.2 CD94.2 CD107.1 CD108.1 CD109.1 CD110.1 CD111.1 CD112.1 PJM2.2 RC1.1 RC2.1 RC627.2 RD1.1 RD32.2 RD42.1 RD46.2 UC1.AC20 UC1.AC21 UC1.AC28 UC1.AD21 UC1.AD23 UC1.AD26 UC1.AD28 UC1.AD32 UC1.AE20 UC1.AE22 UC1.AE25 UC1.AE28 UC1.AF23 UC1.AF26 UC1.AF28 UC1.AF32 UC1.AG20 UC1.AG22 UC1.AG25 UC1.AG28 UC1.AJ20 UC1.AJ23 UC1.AJ26 UC1.AJ28 UC1.AJ32 UC1.AK22 UC1.AK25 UC1.AK28 UC1.AL23 UC1.AL26 UC1.AL28 UC1.AL32 UC1.AM22 UC1.AM25 UC1.AM28 UC1.AN28 UC1.AN32 UC1.AP28 UC1.AR32 UD1.A1 UD1.A9 UD1.B3 UD1.B9 UD1.C1 UD1.D1 UD1.D9 UD1.F2 UD1.F8 UD1.G1 UD1.G7 UD1.G9 UD1.J1 UD1.J2 UD1.J8 UD1.J9 UD1.L1 UD1.L9 UD1.R1 UD1.T9 UD2.A1 UD2.A9 UD2.B3 UD2.B9 UD2.C1 UD2.D1 UD2.D9 UD2.F2 UD2.F8 UD2.G1 UD2.G7 UD2.G9 UD2.J1 UD2.J2 UD2.J8 UD2.J9 UD2.L1 UD2.L9 UD2.R1 UD2.T9 UD3.A1 UD3.A9 UD3.B3 UD3.B9 UD3.C1 UD3.D1 UD3.D9 UD3.F2 UD3.F8 UD3.G1 UD3.G7 UD3.G9 UD3.J1 UD3.J2 UD3.J8 UD3.J9 UD3.L1 UD3.L9 UD3.R1 UD3.T9 UD4.A1 UD4.A9 UD4.B3 UD4.B9 UD4.C1 UD4.D1 UD4.D9 UD4.F2 UD4.F8 UD4.G1 UD4.G7 UD4.G9 UD4.J1 UD4.J2 UD4.J8 UD4.J9 UD4.L1 UD4.L9 UD4.R1 UD4.T9 UD5.A1 UD5.A9 UD5.B3 UD5.B9 UD5.C1 UD5.D1 UD5.D9 UD5.F2 UD5.F8 UD5.G1 UD5.G7 UD5.G9 UD5.J1 UD5.J2 UD5.J8 UD5.J9 UD5.L1 UD5.L9 UD5.R1 UD5.T9 UD6.A1 UD6.A9 UD6.B3 UD6.B9 UD6.C1 UD6.D1 UD6.D9 UD6.F2 UD6.F8 UD6.G1 UD6.G7 UD6.G9 UD6.J1 UD6.J2 UD6.J8 UD6.J9 UD6.L1 UD6.L9 UD6.R1 UD6.T9 UD7.A1 UD7.A9 UD7.B3 UD7.B9 UD7.C1 UD7.D1 UD7.D9 UD7.F2 UD7.F8 UD7.G1 UD7.G7 UD7.G9 UD7.J1 UD7.J2 UD7.J8 UD7.J9 UD7.L1 UD7.L9 UD7.R1 UD7.T9 UD8.A1 UD8.A9 UD8.B3 UD8.B9 UD8.C1 UD8.D1 UD8.D9 UD8.F2 UD8.F8 UD8.G1 UD8.G7 UD8.G9 UD8.J1 UD8.J2 UD8.J8 UD8.J9 UD8.L1 UD8.L9 UD8.R1 UD8.T9
+1.2VP: PCM1.1 PCM3.1 PCM6.1 PCM8.1 PCM15.1 PCM16.1 PJM2.1 PLM1.1 PLM1.2 PRM12.2 PUM1.5 PUM1.19
+1.8V_AUDIO: QA3.1 RA25.1 RA60.1
+1.8VALW: C238.1 C239.1 CC22.1 CC32.1 CC70.1 CC71.1 CC72.1 JHDT1.1 JHDT1.19 PJ1804.2 Q5.1 Q206.2 Q207.2 QA3.3 R75.1 R360.1 RA34.1 RA60.2 RC24.1 RC25.1 RC36.1 RC59.2 RC92.2 RC93.2 RC94.2 RC95.2 RC96.2 RC604.1 RC606.1 RC607.1 RC618.1 RC619.1 RHDT1.2 RHDT2.2 RHDT3.2 RHDT4.2 RHDT5.2 U20.5 UC1.AL19 UC1.AM18 UC2.8
+1.8VALW_1.8VS: J5.2 Q5.3
+1.8VALWP: PC719.1 PC1807.1 PC1808.1 PC9104.1 PJ1804.1 PL1802.2 PR1808.2
+1.8VDD_CODEC: CA6.1 CA24.1 RA25.2 UA1.20
+1.8VS: C1.1 C240.1 C241.1 CC73.1 CC74.1 J5.1 PR1815.1 QC1.2 RC11.2 RC12.2 RC13.2 RC14.2 RC15.2 RC17.2 RC121.1 RC122.1 RC124.1 RC560.1 RC605.2 UC1.AL20 UC1.AM19 UC6.5
+2.5V: CD42.1 CD43.1 CD44.1 CD45.1 CD46.1 CD47.1 CD48.1 CD49.1 CD50.1 CD51.1 CD52.1 CD53.1 CD95.1 CD96.1 CD97.1 CD98.1 CD99.1 CD100.1 CD101.1 CD102.1 CD103.1 CD104.1 CD105.1 CD106.1 PJ252.2 UD1.B1 UD1.R9 UD2.B1 UD2.R9 UD3.B1 UD3.R9 UD4.B1 UD4.R9 UD5.B1 UD5.R9 UD6.B1 UD6.R9 UD7.B1 UD7.R9 UD8.B1 UD8.R9
+2.5VP: PC256.1 PC257.1 PJ252.1 PR252.1 PU251.1 PU251.2 PU251.3
+3V_AUDIO: QA1.1 RA21.1 RA58.1 RT75.1
+3V_CMOS: C230.1 C231.1 JEDP1.31 JEDP1.32 JEDP1.33 JEDP1.34 Q201.1 R337.2
+3V_DMIC: JEDP1.35 R359.2 R360.2
+3V_FP: CFP1.1 JFP1.1 RFP2.2 RFP3.2 RFP4.2
+3V_SD_R: CF7.1 JIO1.23 JIO1.24 RR64.2 RR65.2
+3VALW: C71.1 C72.1 C269.1 CC26.1 CC75.1 CC76.1 CC77.1 CC114.1 CF8.1 CF9.1 CF10.1 CWL61.1 JIO1.22 PC615.1 PC726.1 PJ251.1 PJ302.2 PR719.1 PR1812.1 PU601.15 PU1802.12 Q201.3 Q208.3 Q209.3 QA1.3 QTP1.3 R55.2 R56.2 R57.2 R67.1 R359.1 R4007.1 R4010.2 R4011.2 R4012.2 R4014.1 R4015.1 R4020.2 R4022.2 RA58.2 RC45.1 RC47.1 RC48.1 RC55.1 RC60.2 RC98.1 RC99.1 RC593.1 RC608.1 RC609.1 RC610.1 RC611.1 RC620.2 RC621.2 RC624.1 RC625.1 RKBL3.2 RS4030.1 RS4031.1 RTP5.1 RTP8.2 U10.1 U10.2 UC1.AL17 UC1.AM16 UC7.5 UC8.5 UC23.5 UWL1.5
+3VALW_3VS: J1.2 U10.13 U10.14
+3VALW_EC: C68.1 C69.1 C233.1 C235.1 L1.1 R60.2 R3999.2 R4000.2 UEC1.9 UEC1.22 UEC1.33 UEC1.96 UEC1.125
+3VALWP: PC306.1 PC307.1 PC308.1 PC309.1 PJ302.1 PL301.3 PL301.4 PR304.2 PU301.11
+3VDD_CODEC: CA22.1 RA21.2 UA1.3
+3VL: C234.1 JIO1.36 PJ303.2 PR8.2 PR14.2 PR303.1 PRB29.1 PRB31.1 R62.1 R63.1 R65.1 R66.1 R4000.1 R4023.2 R4026.2 RFP2.1 RUS1.1 RUS4.1 UEC1.111
+3VLP: PC310.1 PC311.1 PJ303.1 PR507.1 PU301.13
+3VS: C4.1 C73.1 C74.1 CC78.1 CC79.1 CC80.1 CTS5.1 J1.1 PR828.2 QH1.2 QH1.5 QH2.2 QH2.5 R64.2 R273.1 R274.1 R337.1 RC4.2 RC5.2 RC28.1 RC29.1 RC31.1 RC56.1 RC57.1 RC62.1 RC63.1 RC85.1 RC89.2 RC90.2 RC91.2 RC112.2 RC568.2 RC574.2 RC614.2 RC616.1 RH13.1 RH23.1 RH24.1 RR64.1 RTP7.1 RTS7.1 U2.5 U5.5 UC1.AL18 UC1.AM17 UC22.5 UTS1.1
+3VS_SSD1: CSD1.1 CSD2.1 CSD3.1 CSD4.1 JSSD1.2 JSSD1.4 JSSD1.12 JSSD1.14 JSSD1.16 JSSD1.18 JSSD1.62 JSSD1.64 JSSD1.66 Q208.1 RSD17.2 USD1.5
+3VS_SSD2: CSD5.1 CSD6.1 CSD7.1 CSD8.1 JSSD2.2 JSSD2.4 JSSD2.12 JSSD2.14 JSSD2.16 JSSD2.18 JSSD2.62 JSSD2.64 JSSD2.66 Q209.1 RSD17.1 USD2.5
+3VS_TP: CTP1.1 JTP1.8 QTP1.1 RTP2.1 RTP7.2 RTP8.1
+3VS_WLAN: CWL1.1 CWL2.1 JWLAN1.2 JWLAN1.4 JWLAN1.64 JWLAN1.66 RR65.1 RWL19.2 UWL22.5
+5V_AUDIO: DA2.5 QA2.1 RA12.2 RA19.1 RA59.2
+5V_DISPLAY: CH5.1 DH1.5 DH1.6 JHDMI1.18 RH25.1 RH26.1 UH1.3
+5V_IN_PWR: CT46.1 CT50.1 CT51.1 QT3.3 RT35.2 RT37.1 UT1.11 UT1.32
+5VALW: C77.1 C78.1 CF6.1 CT68.1 CT71.2 CT74.1 CUS1.1 CUS2.1 CUS3.1 CUS4.1 PC251.2 PJ502.2 PR811.2 PR812.2 PRM6.1 PRM8.1 PU251.10 QA2.3 QT3.1 R54.2 R74.1 R2752.2 RA54.2 RA59.1 RA61.2 RKBL1.1 RT35.1 RT70.1 RUS2.1 U7.1 U9.5 U10.6 U10.7 U19.3 UT4.7 UT6.1
+5VALW_5VS: J2.2 U10.8 U10.9
+5VALW_USB1: CF5.1 JIO1.12 JIO1.13 JIO1.14 JIO1.15 U7.12
+5VALW_USB2: CF13.1 JIO1.17 JIO1.18 JIO1.19 U9.1
+5VALWP: PC509.1 PC510.1 PC511.1 PC512.1 PC513.1 PC514.1 PC515.1 PC516.1 PJ502.1 PL501.3 PL501.4 PR505.2 PU501.14
+5VDDA_CODEC: CA20.1 RA9.2 RA19.2 UA1.40
+5VL: JIO1.20 LED2.2 LED3.2 LED4.2 PJ503.2 U10.4
+5VLP: PC518.1 PJ503.1 PU501.15
+5VS: C79.1 C80.1 CF1.2 CF2.1 CH6.1 J2.1 PC845.2 PR844.2 PR846.2 PU801.33 PU801.34 PU801.41 PU802.1 PU802.8 QKBL1.3 RF2.2 RTP4.2 UH1.1
+5VS_FAN: JFAN2.1 RF2.1
+5VS_KB: JKB2.1 JKB2.31 RTP4.1
+5VS_KBL: CKBL1.1 CKBL2.2 JKBL1.3 JKBL1.4 QKBL1.1
+5VS_PVDD: CA12.1 CA13.1 RA12.1 UA1.41 UA1.46
+12.6V_BATT+: PCB34.1 PQB13.5 PRB9.1
+12.6VB: PCB10.1 PCB13.1 PCB14.1 PCB17.1 PCB26.1 PCB27.1 PJ301.1 PJ501.1 PJ604.1 PJ1803.1 PJM1.1 PL801.2 PL802.2 PQB2.2 PQB13.1 PQB13.2 PQB13.3 PR504.1 PRB32.2 R9.1
+12.6VB_1.8V: PC715.1 PC716.1 PC718.1 PJ1803.2 PU1802.2 PU1802.3 PU1802.4
+12.6VB_3V: PC302.1 PC303.1 PC304.1 PC305.1 PJ301.2 PU301.2 PU301.3 PU301.4
+12.6VB_5V: PC502.1 PC503.1 PC504.1 PC505.1 PC506.1 PC507.1 PJ501.2 PU501.2 PU501.3 PU501.4 PU501.5
+12.6VB_CPU: PC803.1 PC804.1 PC809.1 PC810.1 PC816.1 PC817.1 PC818.1 PC819.1 PC820.1 PC821.1 PC822.1 PC834.1 PC839.1 PC840.1 PC847.1 PC848.1 PL801.1 PL802.1 PQ801.2 PQ802.2 PQ804.2 PQ805.2 PR819.2 PR1814.1
+12.6VB_DDR: PCM4.1 PCM7.1 PCM9.1 PCM12.1 PJM1.2 PQM1.5 PRM10.1
+12.6VB_VDDP: PC601.1 PC604.1 PC605.1 PC622.1 PC623.1 PJ604.2 PU601.2 PU601.3 PU601.4 PU601.5
+19V_ADPIN: PCD2.1 PFD1.2 PLD11.1
+19V_VIN: PCD3.1 PCD4.1 PCD5.1 PDB1.3 PLD11.2 PQD11.1 PQD11.2 PQD11.3 PRB5.1 PRD1.1 PRD6.1
+19V_VIN_P1: PQD4.1 PQD11.5 PQD12.5
+20V_TBT_VBUS_L: PCS1.1 PFS1.2 PQS11.1 PQS11.2 PQS11.3 PRS1.1
+VCC_IO2: C84.1 R3999.1 UEC1.124
